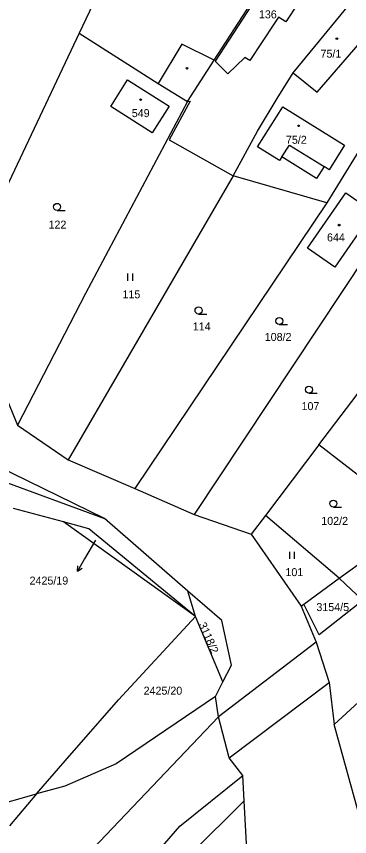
# Model space of a CAD drawing. Extents: x -776734 to -748832, y -1118122 to -976986.
# Drawn here: x -753482.8 to -753412, y -1115665 to -1115490.8 of the extents above; entities that cross this region are included whole.
import ezdxf

# ---------------------------------------------------------------- set-up
doc = ezdxf.new("R2010")
doc.units = 0
for name, color, linetype in [('KM_Hranice parcel', 7, 'Continuous'), ('KM_Parcelní čísla', 7, 'Continuous'), ('KM_Pop  PČ popisy', 7, 'Continuous'), ('KM_Vnitřní kresba', 7, 'Continuous'), ('KM_Značky budov', 7, 'Continuous'), ('KM_Značky kultur', 7, 'Continuous')]:
    doc.layers.add(name, color=color, linetype=linetype)

msp = doc.modelspace()

# ---------------------------------------------------------------- linework, layer by layer
at = {"layer": 'KM_Hranice parcel'}
for p, q in [((-753465.64, -1115486.23), (-753469.5, -1115494.37)), ((-753469.5, -1115494.37), (-753494.92, -1115548.02)), ((-753408.3, -1115516.62), (-753416.84, -1115530.42)), ((-753436.75, -1115524.68), (-753471.82, -1115584.97)), ((-753416.84, -1115530.42), (-753436.75, -1115524.68)), ((-753416.84, -1115530.42), (-753457.68, -1115591.04)), ((-753408.44, -1115541.42), (-753445.02, -1115596.57)), ((-753494.92, -1115548.02), (-753482.6, -1115577.61)), ((-753418.53, -1115581.79), (-753397.6, -1115554.24)), ((-753482.6, -1115577.61), (-753471.82, -1115584.97)), ((-753418.53, -1115581.79), (-753429.91, -1115596.76)), ((-753397.63, -1115598.03), (-753418.53, -1115581.79)), ((-753506.18, -1115582.06), (-753464.09, -1115597.4)), ((-753471.82, -1115584.97), (-753457.68, -1115591.04)), ((-753464.09, -1115597.4), (-753487.15, -1115586.2)), ((-753457.68, -1115591.04), (-753445.02, -1115596.57)), ((-753472.8, -1115598.14), (-753483.46, -1115595.27)), ((-753446.38, -1115612.82), (-753464.09, -1115597.4)), ((-753445.02, -1115596.57), (-753432.94, -1115600.74)), ((-753429.91, -1115596.76), (-753432.94, -1115600.74)), ((-753414.19, -1115610.11), (-753429.91, -1115596.76)), ((-753444.78, -1115618.23), (-753472.8, -1115598.14)), ((-753414.19, -1115610.11), (-753397.63, -1115598.03)), ((-753432.94, -1115600.74), (-753422.27, -1115616.01)), ((-753421.76, -1115615.64), (-753414.19, -1115610.11)), ((-753414.19, -1115610.11), (-753409.19, -1115614.8)), ((-753444.78, -1115618.23), (-753446.38, -1115612.82)), ((-753422.27, -1115616.01), (-753421.76, -1115615.64)), ((-753438.94, -1115632.11), (-753444.78, -1115618.23)), ((-753440.52, -1115635.23), (-753438.94, -1115632.11)), ((-753439.88, -1115639.55), (-753440.52, -1115635.23)), ((-753410.11, -1115636.42), (-753415.28, -1115641.14)), ((-753478.07, -1115679.5), (-753439.88, -1115639.55)), ((-753434.39, -1115657.4), (-753434.69, -1115651.96)), ((-753478.54, -1115655.91), (-753484.31, -1115662.65)), ((-753433.52, -1115673.02), (-753434.39, -1115657.4))]:
    msp.add_line(p, q, dxfattribs=at)
for points in [[(-753446.46, -1115508.92), (-753440.77, -1115500.11), (-753425.38, -1115476.24)], [(-753436.75, -1115524.68), (-753431.6, -1115515.17), (-753427.42, -1115508.28), (-753424, -1115502.82), (-753411.2, -1115487.19)], [(-753469.5, -1115494.37), (-753452.67, -1115505.05), (-753446.46, -1115508.92)], [(-753462.78, -1115509.95), (-753459.22, -1115504.28), (-753450.37, -1115509.86), (-753453.97, -1115515.55), (-753462.78, -1115509.95)], [(-753446.46, -1115508.92), (-753468.15, -1115549.65), (-753482.6, -1115577.61)], [(-753446.46, -1115508.92), (-753445.89, -1115508.81), (-753450.36, -1115517.02), (-753436.75, -1115524.68)], [(-753416.32, -1115523.4), (-753417.41, -1115522.72), (-753419.02, -1115525.27), (-753426.4, -1115520.66), (-753426.89, -1115521.43), (-753431.55, -1115518.51), (-753426.23, -1115510), (-753413.09, -1115518.19), (-753416.32, -1115523.4)], [(-753415.15, -1115544.03), (-753420.96, -1115540), (-753412.83, -1115528.3), (-753407.02, -1115532.32), (-753415.15, -1115544.03)], [(-753444.78, -1115618.23), (-753467.43, -1115599.59), (-753472.8, -1115598.14)], [(-753438.94, -1115632.11), (-753437.13, -1115628.54), (-753439.19, -1115619.07), (-753446.38, -1115612.82)], [(-753409.19, -1115614.8), (-753418.46, -1115622.14), (-753421.76, -1115615.64)], [(-753422.27, -1115616.01), (-753419.11, -1115623.69), (-753416.36, -1115632.25), (-753415.28, -1115641.14)], [(-753478.54, -1115655.91), (-753472.51, -1115648.87), (-753461.16, -1115635.93), (-753444.78, -1115618.23)], [(-753440.52, -1115635.23), (-753461.65, -1115649.52), (-753472.56, -1115654.26), (-753478.54, -1115655.91)], [(-753434.69, -1115651.96), (-753437.61, -1115648.23), (-753439.88, -1115639.55)], [(-753399.68, -1115682.5), (-753402.64, -1115678.68), (-753407.83, -1115669.01), (-753410.02, -1115660.14), (-753415.28, -1115641.14)], [(-753472.17, -1115700.58), (-753461.53, -1115681.87), (-753455.43, -1115671.14), (-753448.13, -1115662.76), (-753434.69, -1115651.96)], [(-753492.76, -1115659.07), (-753488.67, -1115658.7), (-753478.54, -1115655.91)], [(-753461.04, -1115685.36), (-753457.44, -1115680.21), (-753434.39, -1115657.4)]]:
    msp.add_lwpolyline(points, dxfattribs=at)
at = {"layer": 'KM_Pop  PČ popisy'}
for p, q in [((-753466, -1115602.05), (-753468.33, -1115606.02)), ((-753468.33, -1115606.02), (-753469.83, -1115608.619)), ((-753469.83, -1115608.619), (-753469.763, -1115607.501)), ((-753469.83, -1115608.619), (-753468.896, -1115608.002))]:
    msp.add_line(p, q, dxfattribs=at)
at = {"layer": 'KM_Vnitřní kresba'}
for p, q in [((-753432.82, -1115488.39), (-753440.58, -1115500.3)), ((-753422.91, -1115488), (-753425.56, -1115492.01)), ((-753427.15, -1115490.97), (-753427.99, -1115492.25)), ((-753425.56, -1115492.01), (-753427.15, -1115490.97)), ((-753427.99, -1115492.25), (-753433.23, -1115500.21)), ((-753418.93, -1115506.88), (-753405.72, -1115491.69)), ((-753447.67, -1115496.69), (-753452.67, -1115505.05)), ((-753440.77, -1115500.11), (-753447.67, -1115496.69)), ((-753434.28, -1115499.52), (-753437.88, -1115503.05)), ((-753433.23, -1115500.21), (-753434.28, -1115499.52)), ((-753437.88, -1115503.05), (-753440.58, -1115500.3)), ((-753424, -1115502.82), (-753418.93, -1115506.88)), ((-753426.4, -1115520.66), (-753424.79, -1115518.14)), ((-753424.79, -1115518.14), (-753417.41, -1115522.72)), ((-753419.11, -1115623.69), (-753439.88, -1115639.55)), ((-753437.61, -1115648.23), (-753416.36, -1115632.25))]:
    msp.add_line(p, q, dxfattribs=at)
at = {"layer": 'KM_Značky budov'}
for centre in [(-753414.7068, -1115495.5592), (-753446.5768, -1115501.8292), (-753456.4268, -1115508.4892), (-753422.8268, -1115514.0592), (-753414.2168, -1115535.1392)]:
    msp.add_circle(centre, 0.175, dxfattribs=at)
at = {"layer": 'KM_Značky kultur'}
for p, q in [((-753474.203, -1115532.02), (-753472.453, -1115532.02)), ((-753459.121, -1115546.94), (-753459.121, -1115545.44)), ((-753458.12, -1115546.94), (-753458.12, -1115545.44)), ((-753444.113, -1115554.01), (-753442.363, -1115554.01)), ((-753426.943, -1115556.25), (-753425.193, -1115556.25)), ((-753420.643, -1115570.82), (-753418.893, -1115570.82)), ((-753415.453, -1115595.01), (-753413.703, -1115595.01)), ((-753424.681, -1115606.02), (-753424.681, -1115604.52)), ((-753423.68, -1115606.02), (-753423.68, -1115604.52))]:
    msp.add_line(p, q, dxfattribs=at)
for centre in [(-753474.2029, -1115531.2698), (-753444.1129, -1115553.2598), (-753426.9429, -1115555.4998), (-753420.6429, -1115570.0698), (-753415.4529, -1115594.2598)]:
    msp.add_circle(centre, 0.75, dxfattribs=at)

# ---------------------------------------------------------------- texts
at = {"layer": 'KM_Parcelní čísla'}
for s, p in [('136', (-753431.28, -1115491.24)), ('75/1', (-753418.179, -1115499.58)), ('549', (-753458.31, -1115512.21)), ('75/2', (-753425.539, -1115517.87)), ('122', (-753476.01, -1115535.88)), ('644', (-753416.805, -1115538.6)), ('115', (-753460.29, -1115550.68)), ('114', (-753445.35, -1115557.5)), ('108/2', (-753430.04, -1115559.73)), ('107', (-753422.22, -1115574.42)), ('102/2', (-753418.02, -1115598.78)), ('101', (-753425.64, -1115609.66)), ('2425/19', (-753480.043, -1115611.458)), ('3154/5', (-753419.06, -1115617.08)), ('2425/20', (-753455.8, -1115634.83))]:
    msp.add_text(s, height=1.7, dxfattribs=at).set_placement(p)
msp.add_text('3118/2', height=1.7, rotation=294, dxfattribs=at).set_placement((-753444.146, -1115619.925))

doc.saveas('drawing.dxf')
